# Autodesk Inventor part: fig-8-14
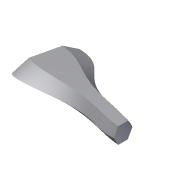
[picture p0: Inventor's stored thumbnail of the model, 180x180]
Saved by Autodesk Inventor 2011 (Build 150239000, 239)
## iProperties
Created: 2004-05
Part Number: fig-8-14
Document SubType Name: Modeling
Designer: CADCIM Technologies
Manufacturer: Standard
Standards Organization: Custom
Density: 1 g/cm^3
Author: CADCIM Technologies
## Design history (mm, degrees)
workplane "Work Plane2"
sketch "Sketch7"
  geometry: L1 (-42.583, 6.068)-(-42.583, 0.37) reference; 5 further points
  constraints: 1 point on line, 5 other
sketch "Sketch8"
  geometry: L1 (-42.583, 3.219)-(-107.269, 18.236); L2 (-42.583, 6.068)-(-42.583, 0.37) reference
  constraints: 2 end point, 1 midpoint
sweep "Sweep7" sketch "Sketch7", "Sketch8" dims "d6" = 0
body "Solid1"
sketch "Sketch2"
  geometry: L1 (-5.697, 0)-(-2.849, 4.934); L2 (-2.849, 4.934)-(2.849, 4.934); L3 (2.849, 4.934)-(5.697, 0); L4 (5.697, 0)-(2.849, -4.934); L5 (2.849, -4.934)-(-2.849, -4.934); L6 (-2.849, -4.934)-(-5.697, 0); 2 further points
  constraints: 12 end point, 1 coincident, 12 other
